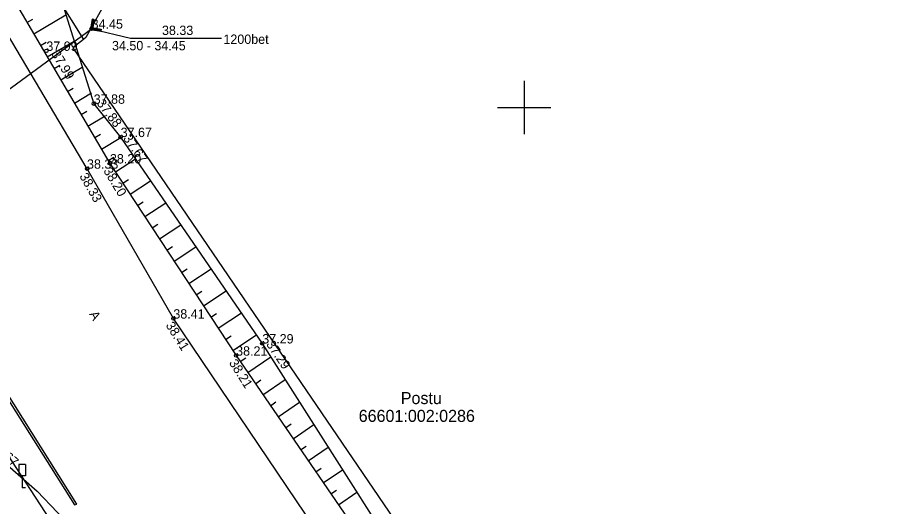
# Model space of a CAD drawing. Extents: x 627548 to 628052, y 6467984 to 6468802.
# Drawn here: x 627662.1 to 627728.3, y 6468670.2 to 6468706.7 of the extents above; entities that cross this region are included whole.
import ezdxf

# ---------------------------------------------------------------- set-up
doc = ezdxf.new("R2010")
doc.units = 0
for name, color, linetype in [('KORGUS-EH2000', 7, 'Continuous'), ('LIIKLUS', 7, 'Continuous'), ('MOOTKORG-EH2000', 7, 'Continuous'), ('MOOTMPUNKT', 7, 'Continuous'), ('PIIR', 7, 'Continuous'), ('RELJEEF', 7, 'Continuous'), ('TEE', 7, 'Continuous'), ('TRUUP', 7, 'Continuous'), ('VORK', 7, 'Continuous')]:
    doc.layers.add(name, color=color, linetype=linetype)

msp = doc.modelspace()

# ---------------------------------------------------------------- linework, layer by layer
at = {"layer": 'LIIKLUS'}
for points in [[(627662.174, 6468673.287), (627662.174, 6468672.437)], [(627662.674, 6468673.287), (627662.174, 6468673.287)], [(627662.674, 6468673.287), (627662.674, 6468672.437)], [(627662.674, 6468672.437), (627662.174, 6468672.437)], [(627662.424, 6468672.437), (627662.424, 6468671.537)], [(627662.674, 6468671.537), (627662.424, 6468671.537)]]:
    msp.add_lwpolyline(points, dxfattribs=at)
at = {"layer": 'MOOTMPUNKT'}
for centre in [(627667.616, 6468705.898), (627664.227, 6468704.241), (627667.771, 6468700.282), (627669.788, 6468697.789), (627668.985, 6468695.815), (627667.271, 6468695.423), (627673.734, 6468684.205), (627680.393, 6468682.345), (627678.436, 6468681.433)]:
    msp.add_circle(centre, 0.125, dxfattribs=at)
at = {"layer": 'PIIR'}
for p, q in [((627669.44, 6468709.31), (627667.19, 6468705.25)), ((627664.81, 6468708.59), (627667, 6468705.1)), ((627667.19, 6468705.25), (627667, 6468705.1)), ((627667, 6468705.1), (627666.22, 6468704.47)), ((627666.22, 6468704.47), (627739.66, 6468596.76)), ((627667.34, 6468664.86), (627649.05, 6468692.73))]:
    msp.add_line(p, q, dxfattribs=at)
at = {"layer": 'RELJEEF'}
for p, q in [((627662.771, 6468706.369), (627663.202, 6468706.622)), ((627663.279, 6468705.507), (627665.69, 6468706.927)), ((627663.786, 6468704.645), (627664.217, 6468704.899)), ((627664.293, 6468703.784), (627666.304, 6468704.967)), ((627664.801, 6468702.922), (627665.232, 6468703.176)), ((627665.308, 6468702.06), (627666.917, 6468703.008)), ((627665.815, 6468701.198), (627666.246, 6468701.452)), ((627666.323, 6468700.337), (627667.615, 6468701.098)), ((627666.83, 6468699.475), (627667.261, 6468699.729)), ((627667.337, 6468698.613), (627668.63, 6468699.374)), ((627667.845, 6468697.751), (627668.276, 6468698.005)), ((627668.352, 6468696.89), (627669.814, 6468697.751)), ((627668.86, 6468696.028), (627669.29, 6468696.282)), ((627669.398, 6468695.186), (627670.899, 6468696.172)), ((627669.948, 6468694.35), (627670.365, 6468694.625)), ((627670.497, 6468693.514), (627672.031, 6468694.523)), ((627671.046, 6468692.679), (627671.464, 6468692.953)), ((627671.595, 6468691.843), (627673.163, 6468692.874)), ((627672.144, 6468691.007), (627672.562, 6468691.282)), ((627672.693, 6468690.172), (627674.296, 6468691.225)), ((627673.243, 6468689.336), (627673.661, 6468689.611)), ((627673.792, 6468688.5), (627675.428, 6468689.575)), ((627674.341, 6468687.665), (627674.759, 6468687.939)), ((627674.89, 6468686.829), (627676.56, 6468687.926)), ((627675.439, 6468685.993), (627675.857, 6468686.268)), ((627675.989, 6468685.157), (627677.693, 6468686.277)), ((627676.538, 6468684.322), (627676.956, 6468684.596)), ((627677.087, 6468683.486), (627678.825, 6468684.628)), ((627677.636, 6468682.65), (627678.054, 6468682.925)), ((627678.185, 6468681.815), (627679.958, 6468682.979)), ((627678.743, 6468680.985), (627679.156, 6468681.268)), ((627679.309, 6468680.16), (627681.031, 6468681.341)), ((627679.874, 6468679.335), (627680.287, 6468679.618)), ((627680.44, 6468678.511), (627682.104, 6468679.652)), ((627681.005, 6468677.686), (627681.418, 6468677.969)), ((627681.571, 6468676.861), (627683.178, 6468677.963)), ((627682.136, 6468676.036), (627682.549, 6468676.319)), ((627682.702, 6468675.212), (627684.251, 6468676.274)), ((627683.267, 6468674.387), (627683.68, 6468674.67)), ((627683.833, 6468673.562), (627685.324, 6468674.585)), ((627684.398, 6468672.737), (627684.811, 6468673.02)), ((627684.964, 6468671.913), (627686.397, 6468672.896)), ((627685.529, 6468671.088), (627685.942, 6468671.37)), ((627686.095, 6468670.263), (627687.471, 6468671.207))]:
    msp.add_line(p, q, dxfattribs=at)
for points in [[(627624.669, 6468783.336), (627635.143, 6468764.467), (627644.826, 6468744.62), (627663.453, 6468714.069), (627667.771, 6468700.282), (627669.788, 6468697.789), (627680.393, 6468682.345), (627695.175, 6468659.082), (627697.462, 6468659.655)], [(627621.271, 6468781.45), (627631.48, 6468762.833), (627641.678, 6468741.628), (627656.496, 6468717.027), (627668.985, 6468695.815), (627678.436, 6468681.433), (627690.541, 6468663.778), (627694.507, 6468657.515), (627696.664, 6468657.822), (627698.617, 6468658.584)]]:
    msp.add_lwpolyline(points, dxfattribs=at)
at = {"layer": 'TEE'}
for points in [[(627700.939, 6468658.86), (627696.392, 6468656.072), (627693.013, 6468655.978), (627687.872, 6468663.274), (627673.734, 6468684.205), (627667.271, 6468695.423), (627655.655, 6468715.038), (627640.744, 6468741.218), (627629.668, 6468761.293)], [(627642.851, 6468701.697), (627643.652, 6468701.039), (627643.972, 6468700.891), (627645.246, 6468699.098), (627649.286, 6468692.707), (627654.27, 6468685.483), (627656.176, 6468682.398), (627657.145, 6468678.821), (627659.852, 6468674.505), (627663.528, 6468671.281), (627666.594, 6468668.111), (627670.77, 6468663.802), (627676.196, 6468657.041), (627682.033, 6468649.275), (627691.556, 6468636.216), (627691.146, 6468633.38), (627690.377, 6468632.362), (627683.705, 6468630.285), (627675.534, 6468628.326)], [(627656.072, 6468686.492), (627666.322, 6468670.277), (627666.512, 6468670.325)], [(627666.512, 6468670.325), (627656.241, 6468686.596)]]:
    msp.add_lwpolyline(points, dxfattribs=at)
at = {"layer": 'TRUUP'}
for p, q in [((627667.649, 6468706.608), (627667.535, 6468705.838)), ((627667.782, 6468706.534), (627667.6, 6468706.275)), ((627667.789, 6468706.587), (627667.608, 6468706.33)), ((627667.719, 6468706.598), (627667.616, 6468705.898)), ((627667.761, 6468706.591), (627667.616, 6468706.385)), ((627667.733, 6468706.595), (627667.624, 6468706.44)), ((627667.706, 6468706.6), (627667.632, 6468706.495)), ((627667.678, 6468706.604), (627667.64, 6468706.55)), ((627667.79, 6468706.587), (627667.649, 6468706.608)), ((627667.79, 6468706.587), (627667.697, 6468705.958)), ((627667.717, 6468706.094), (627667.536, 6468705.838)), ((627667.725, 6468706.149), (627667.543, 6468705.891)), ((627667.733, 6468706.204), (627667.551, 6468705.946)), ((627667.741, 6468706.259), (627667.559, 6468706.001)), ((627667.709, 6468706.039), (627667.564, 6468705.834)), ((627667.749, 6468706.314), (627667.567, 6468706.056)), ((627667.758, 6468706.369), (627667.575, 6468706.111)), ((627667.766, 6468706.424), (627667.584, 6468706.166)), ((627667.774, 6468706.479), (627667.592, 6468706.22)), ((627667.701, 6468705.985), (627667.592, 6468705.83)), ((627667.616, 6468705.898), (627668.316, 6468705.795)), ((627667.711, 6468705.956), (627667.619, 6468705.826)), ((627667.739, 6468705.952), (627667.647, 6468705.821)), ((627667.767, 6468705.948), (627667.675, 6468705.817)), ((627667.697, 6468705.958), (627668.326, 6468705.865)), ((627667.794, 6468705.944), (627667.702, 6468705.813)), ((627667.822, 6468705.94), (627667.73, 6468705.809)), ((627667.85, 6468705.935), (627667.758, 6468705.805)), ((627667.877, 6468705.931), (627667.786, 6468705.801)), ((627667.905, 6468705.927), (627667.813, 6468705.797)), ((627667.933, 6468705.923), (627667.841, 6468705.793)), ((627667.96, 6468705.919), (627667.869, 6468705.789)), ((627667.988, 6468705.915), (627667.896, 6468705.785)), ((627668.016, 6468705.911), (627667.924, 6468705.781)), ((627668.043, 6468705.907), (627667.952, 6468705.776)), ((627668.071, 6468705.903), (627667.979, 6468705.772)), ((627668.099, 6468705.899), (627668.007, 6468705.768)), ((627668.127, 6468705.894), (627668.035, 6468705.764)), ((627668.154, 6468705.89), (627668.062, 6468705.76)), ((627668.182, 6468705.886), (627668.09, 6468705.756)), ((627668.21, 6468705.882), (627668.118, 6468705.752)), ((627668.237, 6468705.878), (627668.146, 6468705.748)), ((627668.265, 6468705.874), (627668.173, 6468705.744)), ((627668.293, 6468705.87), (627668.201, 6468705.74)), ((627667.535, 6468705.838), (627668.305, 6468705.724)), ((627668.32, 6468705.866), (627668.229, 6468705.735)), ((627668.319, 6468705.821), (627668.256, 6468705.731)), ((627668.311, 6468705.766), (627668.284, 6468705.727)), ((627668.326, 6468705.865), (627668.305, 6468705.724))]:
    msp.add_line(p, q, dxfattribs=at)
for points in [[(627644.203, 6468688.747), (627667.616, 6468705.898)], [(627667.616, 6468705.898), (627670.537, 6468705.182)], [(627670.537, 6468705.182), (627677.347, 6468705.182)]]:
    msp.add_lwpolyline(points, dxfattribs=at)
at = {"layer": 'VORK'}
for p, q in [((627700, 6468702), (627700, 6468698)), ((627698, 6468700), (627702, 6468700))]:
    msp.add_line(p, q, dxfattribs=at)

# ---------------------------------------------------------------- texts
at = {"layer": 'KORGUS-EH2000'}
for s, rotation, p in [('37.99', 301.13774, (627664.566, 6468704.03)), ('37.88', 307.27339, (627667.958, 6468700.305)), ('37.67', 304.97824, (627669.945, 6468697.689)), ('38.20', 301.0895, (627668.468, 6468695.267)), ('38.33', 299.25679, (627666.681, 6468694.87)), ('38.41', 302.11231, (627673.132, 6468683.707)), ('37.29', 303.96025, (627680.657, 6468682.284)), ('38.21', 302.38862, (627677.872, 6468680.896)), (' 38.67', 318.74793, (627659.808, 6468674.798))]:
    msp.add_text(s, height=0.7, rotation=rotation, dxfattribs=at).set_placement(p)
at = {"layer": 'MOOTKORG-EH2000'}
for s, p in [('34.45', (627667.616, 6468705.898)), ('37.99', (627664.227, 6468704.241)), ('37.88', (627667.771, 6468700.282)), ('37.67', (627669.788, 6468697.789)), ('38.33', (627667.271, 6468695.423)), ('38.20', (627668.985, 6468695.815)), ('38.41', (627673.734, 6468684.205)), ('37.29', (627680.393, 6468682.345)), ('38.21', (627678.436, 6468681.433))]:
    msp.add_text(s, height=0.7, dxfattribs=at).set_placement(p)
at = {"layer": 'PIIR'}
for s, p in [('Postu', (627690.762, 6468677.807)), ('66601:002:0286', (627687.612, 6468676.476))]:
    msp.add_text(s, height=0.9, dxfattribs=at).set_placement(p)
at = {"layer": 'TEE'}
msp.add_text('A', height=0.7, rotation=299.16562, dxfattribs=at).set_placement((627667.424, 6468684.542))
at = {"layer": 'TRUUP'}
for s, p in [(' 38.33', (627672.623, 6468705.427)), ('1200bet', (627677.484, 6468704.762)), (' 34.50 - 34.45', (627668.882, 6468704.281))]:
    msp.add_text(s, height=0.7, dxfattribs=at).set_placement(p)

doc.saveas('drawing.dxf')
